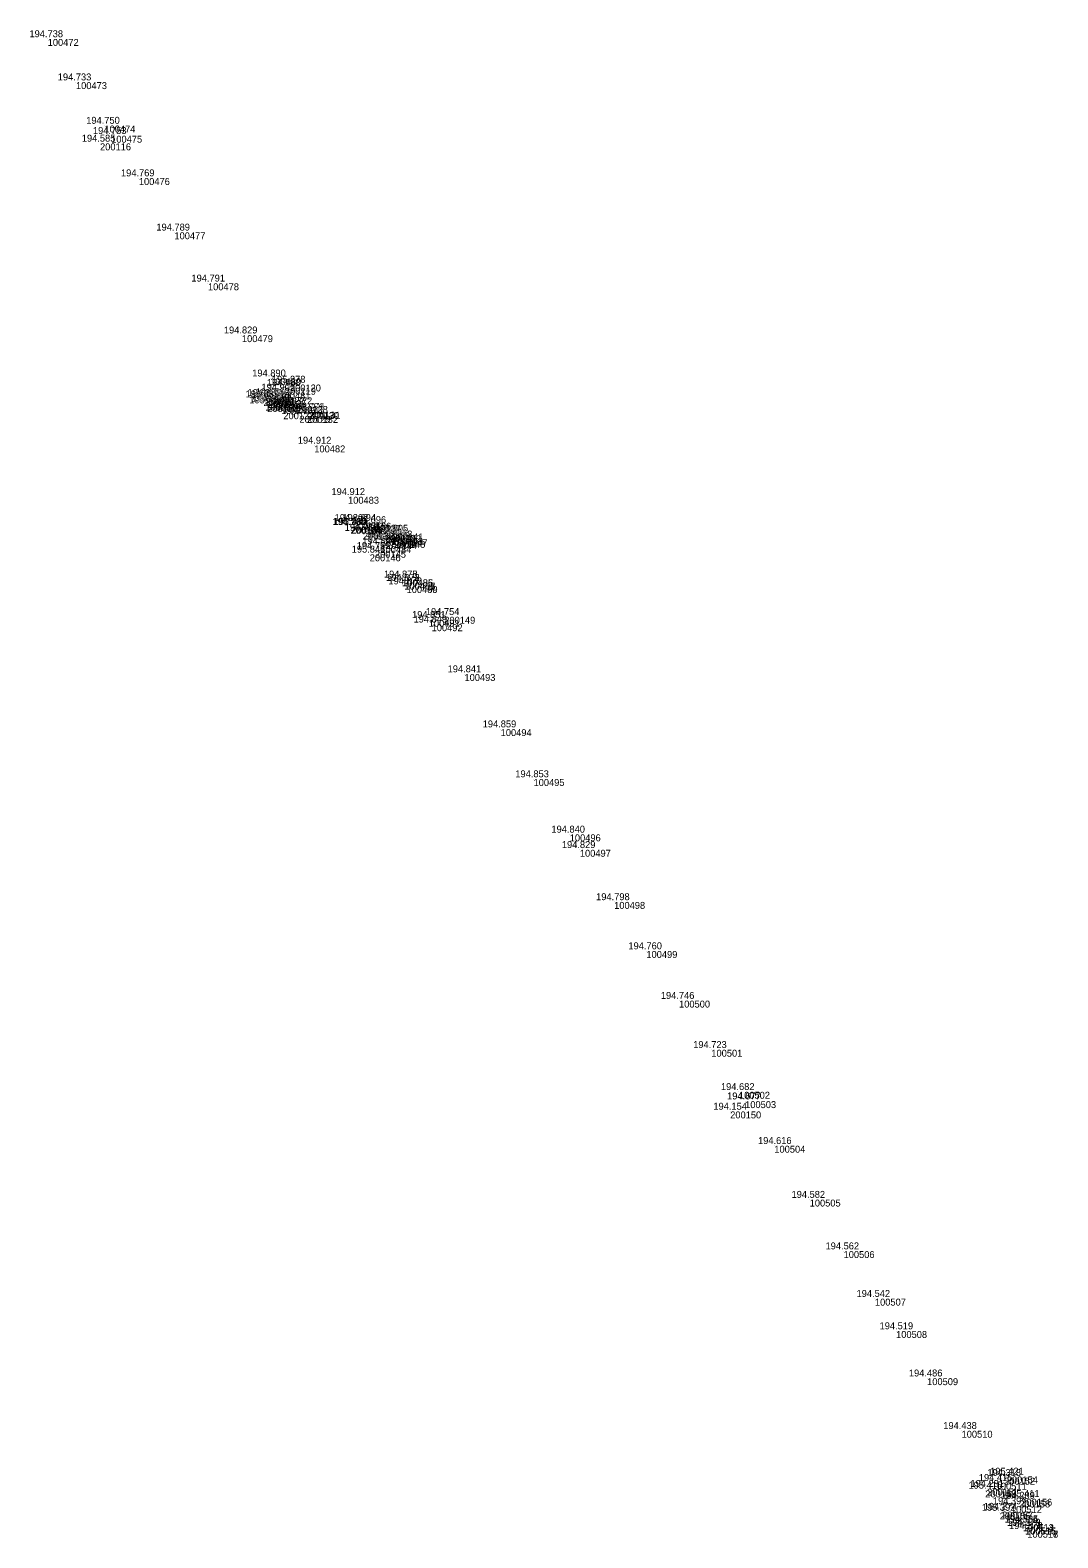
# Model space of a CAD drawing. Extents: x -545715 to -485912, y -1154994 to -1140055.
# Drawn here: x -543663.7 to -543486.1, y -1151376.1 to -1151115.3 of the extents above; entities that cross this region are included whole.
import ezdxf

# ---------------------------------------------------------------- set-up
doc = ezdxf.new("R2010")
doc.units = 0
doc.layers.add('Vrstva 60', color=7, linetype='Continuous')
doc.layers.add('Vrstva 61', color=7, linetype='Continuous')

msp = doc.modelspace()

# ---------------------------------------------------------------- linework, layer by layer
at = {"layer": 'Vrstva 60'}
for p, q in [((-543660.72, -1151116.84), (-543660.72, -1151116.84)), ((-543655.83, -1151124.31), (-543655.83, -1151124.31)), ((-543650.91, -1151131.81), (-543650.91, -1151131.81)), ((-543649.75, -1151133.58), (-543649.75, -1151133.58)), ((-543651.67, -1151134.91), (-543651.67, -1151134.91)), ((-543644.96, -1151140.9), (-543644.96, -1151140.9)), ((-543638.81, -1151150.28), (-543638.81, -1151150.28)), ((-543633.01, -1151159.1), (-543633.01, -1151159.1)), ((-543627.14, -1151168.07), (-543627.14, -1151168.07)), ((-543622.25, -1151175.51), (-543622.25, -1151175.51)), ((-543623.01, -1151178.89), (-543623.01, -1151178.89)), ((-543621.64, -1151178.78), (-543621.64, -1151178.78)), ((-543620.65, -1151177.96), (-543620.65, -1151177.96)), ((-543619.7, -1151177.16), (-543619.7, -1151177.16)), ((-543618.84, -1151176.6), (-543618.84, -1151176.6)), ((-543623.42, -1151179.14), (-543623.42, -1151179.14)), ((-543622.76, -1151180.16), (-543622.76, -1151180.16)), ((-543622.66, -1151179.44), (-543622.66, -1151179.44)), ((-543622.3, -1151179.86), (-543622.3, -1151179.86)), ((-543621.44, -1151179.95), (-543621.44, -1151179.95)), ((-543621.28, -1151179.31), (-543621.28, -1151179.31)), ((-543619.98, -1151181.4), (-543619.98, -1151181.4)), ((-543617.64, -1151180.3), (-543617.64, -1151180.3)), ((-543615.68, -1151181.36), (-543615.68, -1151181.36)), ((-543615.47, -1151181.31), (-543615.47, -1151181.31)), ((-543617.2, -1151182.01), (-543617.2, -1151182.01)), ((-543615.89, -1151182.04), (-543615.89, -1151182.04)), ((-543614.63, -1151187.14), (-543614.63, -1151187.14)), ((-543608.8, -1151196.02), (-543608.8, -1151196.02)), ((-543608.37, -1151201.21), (-543608.37, -1151201.21)), ((-543608.22, -1151201.18), (-543608.22, -1151201.18)), ((-543607.97, -1151200.52), (-543607.97, -1151200.52)), ((-543606.68, -1151200.51), (-543606.68, -1151200.51)), ((-543606.24, -1151202.21), (-543606.24, -1151202.21)), ((-543604.98, -1151200.87), (-543604.98, -1151200.87)), ((-543601.11, -1151202.36), (-543601.11, -1151202.36)), ((-543603.21, -1151204.55), (-543603.21, -1151204.55)), ((-543602.6, -1151203.26), (-543602.6, -1151203.26)), ((-543602.4, -1151202.6), (-543602.4, -1151202.6)), ((-543602.2, -1151203.84), (-543602.2, -1151203.84)), ((-543601.54, -1151202.68), (-543601.54, -1151202.68)), ((-543601.17, -1151203.15), (-543601.17, -1151203.15)), ((-543600.8, -1151203.65), (-543600.8, -1151203.65)), ((-543600.4, -1151203.36), (-543600.4, -1151203.36)), ((-543605.05, -1151205.97), (-543605.05, -1151205.97)), ((-543604.14, -1151205.36), (-543604.14, -1151205.36)), ((-543599.45, -1151210.28), (-543599.45, -1151210.28)), ((-543599.44, -1151210.29), (-543599.44, -1151210.29)), ((-543599.07, -1151210.86), (-543599.07, -1151210.86)), ((-543599.06, -1151210.86), (-543599.06, -1151210.86)), ((-543598.68, -1151211.45), (-543598.68, -1151211.45)), ((-543598.68, -1151211.45), (-543598.68, -1151211.45)), ((-543594.85, -1151217.29), (-543594.85, -1151217.29)), ((-543594.34, -1151218.06), (-543594.34, -1151218.06)), ((-543592.16, -1151216.77), (-543592.16, -1151216.77)), ((-543588.67, -1151226.67), (-543588.67, -1151226.67)), ((-543582.41, -1151236.2), (-543582.41, -1151236.2)), ((-543576.73, -1151244.83), (-543576.73, -1151244.83)), ((-543570.47, -1151254.4), (-543570.47, -1151254.4)), ((-543568.72, -1151257.07), (-543568.72, -1151257.07)), ((-543562.79, -1151266.08), (-543562.79, -1151266.08)), ((-543557.22, -1151274.57), (-543557.22, -1151274.57)), ((-543551.57, -1151283.15), (-543551.57, -1151283.15)), ((-543545.99, -1151291.65), (-543545.99, -1151291.65)), ((-543541.21, -1151298.92), (-543541.21, -1151298.92)), ((-543540.15, -1151300.54), (-543540.15, -1151300.54)), ((-543542.73, -1151302.32), (-543542.73, -1151302.32)), ((-543535.1, -1151308.25), (-543535.1, -1151308.25)), ((-543528.99, -1151317.56), (-543528.99, -1151317.56)), ((-543523.13, -1151326.47), (-543523.13, -1151326.47)), ((-543517.71, -1151334.7), (-543517.71, -1151334.7)), ((-543514.05, -1151340.29), (-543514.05, -1151340.29)), ((-543508.69, -1151348.45), (-543508.69, -1151348.45)), ((-543502.73, -1151357.54), (-543502.73, -1151357.54)), ((-543496.83, -1151366.53), (-543496.83, -1151366.53)), ((-543495.38, -1151365.66), (-543495.38, -1151365.66)), ((-543494.91, -1151365.44), (-543494.91, -1151365.44)), ((-543498.65, -1151367.85), (-543498.65, -1151367.85)), ((-543498.31, -1151367.55), (-543498.31, -1151367.55)), ((-543492.42, -1151369.3), (-543492.42, -1151369.3)), ((-543496.14, -1151371.68), (-543496.14, -1151371.68)), ((-543495.72, -1151371.51), (-543495.72, -1151371.51)), ((-543494.2, -1151370.55), (-543494.2, -1151370.55)), ((-543492.77, -1151369.6), (-543492.77, -1151369.6)), ((-543492.13, -1151373.69), (-543492.13, -1151373.69)), ((-543492.12, -1151373.71), (-543492.12, -1151373.71)), ((-543491.77, -1151374.24), (-543491.77, -1151374.24)), ((-543491.74, -1151374.29), (-543491.74, -1151374.29)), ((-543491.38, -1151374.83), (-543491.38, -1151374.83)), ((-543491.38, -1151374.84), (-543491.38, -1151374.84))]:
    msp.add_line(p, q, dxfattribs=at)

# ---------------------------------------------------------------- texts
for s, p in [('100472', (-543660.72, -1151118.04)), ('100473', (-543655.83, -1151125.51)), ('100474', (-543650.91, -1151133.01)), ('100475', (-543649.75, -1151134.78)), ('200116', (-543651.67, -1151136.1)), ('100476', (-543644.96, -1151142.1)), ('100477', (-543638.81, -1151151.48)), ('100478', (-543633.01, -1151160.3)), ('100479', (-543627.14, -1151169.27)), ('100480', (-543622.25, -1151176.71)), ('200118', (-543623.01, -1151180.09)), ('200122', (-543621.64, -1151179.98)), ('100481', (-543620.65, -1151179.16)), ('200119', (-543619.7, -1151178.36)), ('200120', (-543618.84, -1151177.8)), ('200117', (-543623.42, -1151180.34)), ('200123', (-543622.76, -1151181.36)), ('200121', (-543622.66, -1151180.64)), ('200124', (-543622.3, -1151181.06)), ('200126', (-543621.44, -1151181.15)), ('200125', (-543621.28, -1151180.51)), ('200127', (-543619.98, -1151182.6)), ('200128', (-543617.64, -1151181.51)), ('200130', (-543615.68, -1151182.56)), ('200131', (-543615.47, -1151182.51)), ('200129', (-543617.2, -1151183.21)), ('200132', (-543615.89, -1151183.24)), ('100482', (-543614.63, -1151188.34)), ('100483', (-543608.8, -1151197.22)), ('200134', (-543608.37, -1151202.41)), ('200135', (-543608.22, -1151202.38)), ('200133', (-543607.97, -1151201.72)), ('200136', (-543606.68, -1151201.71)), ('200138', (-543606.24, -1151203.41)), ('200137', (-543604.98, -1151202.07)), ('200141', (-543601.11, -1151203.56)), ('100484', (-543603.21, -1151205.75)), ('200140', (-543602.6, -1151204.46)), ('200139', (-543602.4, -1151203.8)), ('200144', (-543602.2, -1151205.04)), ('200142', (-543601.54, -1151203.88)), ('200143', (-543601.17, -1151204.35)), ('200148', (-543600.8, -1151204.85)), ('200147', (-543600.4, -1151204.56)), ('200146', (-543605.05, -1151207.17)), ('200145', (-543604.14, -1151206.56)), ('100485', (-543599.45, -1151211.48)), ('100486', (-543599.44, -1151211.49)), ('100487', (-543599.07, -1151212.06)), ('100488', (-543599.06, -1151212.06)), ('100489', (-543598.68, -1151212.65)), ('100490', (-543598.68, -1151212.65)), ('100491', (-543594.85, -1151218.49)), ('100492', (-543594.34, -1151219.26)), ('200149', (-543592.16, -1151217.97)), ('100493', (-543588.67, -1151227.87)), ('100494', (-543582.41, -1151237.4)), ('100495', (-543576.73, -1151246.03)), ('100496', (-543570.47, -1151255.6)), ('100497', (-543568.72, -1151258.27)), ('100498', (-543562.79, -1151267.28)), ('100499', (-543557.22, -1151275.77)), ('100500', (-543551.57, -1151284.35)), ('100501', (-543545.99, -1151292.85)), ('100502', (-543541.21, -1151300.12)), ('100503', (-543540.15, -1151301.74)), ('200150', (-543542.73, -1151303.52)), ('100504', (-543535.1, -1151309.45)), ('100505', (-543528.99, -1151318.76)), ('100506', (-543523.13, -1151327.67)), ('100507', (-543517.71, -1151335.9)), ('100508', (-543514.05, -1151341.49)), ('100509', (-543508.69, -1151349.65)), ('100510', (-543502.73, -1151358.74)), ('100511', (-543496.83, -1151367.73)), ('200152', (-543495.38, -1151366.86)), ('200154', (-543494.91, -1151366.64)), ('200153', (-543498.65, -1151369.05)), ('200151', (-543498.31, -1151368.75)), ('200156', (-543492.42, -1151370.5)), ('200155', (-543496.14, -1151372.88)), ('200157', (-543495.72, -1151372.71)), ('100512', (-543494.2, -1151371.75)), ('200158', (-543492.77, -1151370.8)), ('100513', (-543492.13, -1151374.89)), ('100514', (-543492.12, -1151374.91)), ('100515', (-543491.77, -1151375.44)), ('100516', (-543491.74, -1151375.49)), ('100517', (-543491.38, -1151376.03)), ('100518', (-543491.38, -1151376.04))]:
    msp.add_text(s, height=1.2, dxfattribs=at).set_placement(p)
at = {"layer": 'Vrstva 61'}
for s, p in [('194.738', (-543663.87, -1151116.54)), ('194.733', (-543658.98, -1151124.01)), ('194.750', (-543654.06, -1151131.51)), ('194.585', (-543654.82, -1151134.6)), ('194.753', (-543652.9, -1151133.28)), ('194.769', (-543648.05, -1151140.6)), ('194.789', (-543641.93, -1151149.98)), ('194.791', (-543635.87, -1151158.8)), ('194.829', (-543630.26, -1151167.77)), ('194.890', (-543625.36, -1151175.21)), ('194.768', (-543622.82, -1151176.86)), ('195.878', (-543621.96, -1151176.3)), ('195.889', (-543626.51, -1151178.84)), ('194.775', (-543626.17, -1151178.59)), ('195.895', (-543625.85, -1151179.86)), ('194.781', (-543625.55, -1151179.14)), ('195.889', (-543625.38, -1151179.56)), ('194.769', (-543624.74, -1151178.48)), ('194.784', (-543624.62, -1151179.65)), ('194.773', (-543624.44, -1151179.01)), ('194.905', (-543623.76, -1151177.66)), ('194.772', (-543620.79, -1151180.01)), ('193.703', (-543623.09, -1151181.1)), ('193.702', (-543620.32, -1151181.71)), ('195.886', (-543618.77, -1151181.06)), ('194.801', (-543618.77, -1151181.74)), ('194.774', (-543618.65, -1151181.01)), ('194.912', (-543617.48, -1151186.84)), ('194.912', (-543611.66, -1151195.72)), ('194.760', (-543611.49, -1151200.91)), ('195.880', (-543611.33, -1151200.88)), ('194.802', (-543611.11, -1151200.22)), ('193.694', (-543609.76, -1151200.21)), ('193.696', (-543608.01, -1151200.57)), ('194.756', (-543609.36, -1151201.91)), ('194.767', (-543605.72, -1151202.96)), ('194.795', (-543605.52, -1151202.3)), ('194.768', (-543605.32, -1151203.54)), ('195.895', (-543604.63, -1151202.38)), ('194.778', (-543604.33, -1151202.85)), ('195.895', (-543604.19, -1151202.06)), ('194.786', (-543603.92, -1151203.35)), ('195.903', (-543603.48, -1151203.06)), ('195.846', (-543608.16, -1151205.67)), ('194.755', (-543607.29, -1151205.06)), ('194.894', (-543606.35, -1151204.25)), ('194.875', (-543602.59, -1151209.98)), ('194.873', (-543602.59, -1151209.99)), ('194.873', (-543602.22, -1151210.56)), ('194.872', (-543602.21, -1151210.56)), ('194.870', (-543601.82, -1151211.15)), ('194.870', (-543601.82, -1151211.15)), ('194.754', (-543595.34, -1151216.47)), ('194.851', (-543597.73, -1151216.99)), ('194.849', (-543597.48, -1151217.76)), ('194.841', (-543591.58, -1151226.37)), ('194.859', (-543585.52, -1151235.9)), ('194.853', (-543579.88, -1151244.53)), ('194.840', (-543573.64, -1151254.1)), ('194.829', (-543571.83, -1151256.77)), ('194.798', (-543565.91, -1151265.78)), ('194.760', (-543560.33, -1151274.27)), ('194.746', (-543554.72, -1151282.85)), ('194.723', (-543549.13, -1151291.35)), ('194.682', (-543544.33, -1151298.62)), ('194.154', (-543545.64, -1151302.02)), ('194.677', (-543543.27, -1151300.24)), ('194.616', (-543537.92, -1151307.95)), ('194.582', (-543532.13, -1151317.26)), ('194.562', (-543526.25, -1151326.17)), ('194.542', (-543520.89, -1151334.4)), ('194.519', (-543516.91, -1151339.99)), ('194.486', (-543511.84, -1151348.15)), ('194.438', (-543505.9, -1151357.24)), ('195.421', (-543497.79, -1151365.14)), ('195.415', (-543501.53, -1151367.55)), ('194.281', (-543501.2, -1151367.25)), ('194.415', (-543499.75, -1151366.23)), ('194.318', (-543498.26, -1151365.36)), ('194.397', (-543497.32, -1151370.25)), ('194.289', (-543495.88, -1151369.3)), ('195.411', (-543495.04, -1151369)), ('195.392', (-543499.22, -1151371.38)), ('194.274', (-543498.9, -1151371.21)), ('194.384', (-543495.29, -1151373.41)), ('194.385', (-543495.28, -1151373.39)), ('194.379', (-543494.89, -1151373.94)), ('194.378', (-543494.88, -1151373.99)), ('194.370', (-543494.52, -1151374.53)), ('194.372', (-543494.52, -1151374.54))]:
    msp.add_text(s, height=1.2, dxfattribs=at).set_placement(p)

doc.saveas('drawing.dxf')
